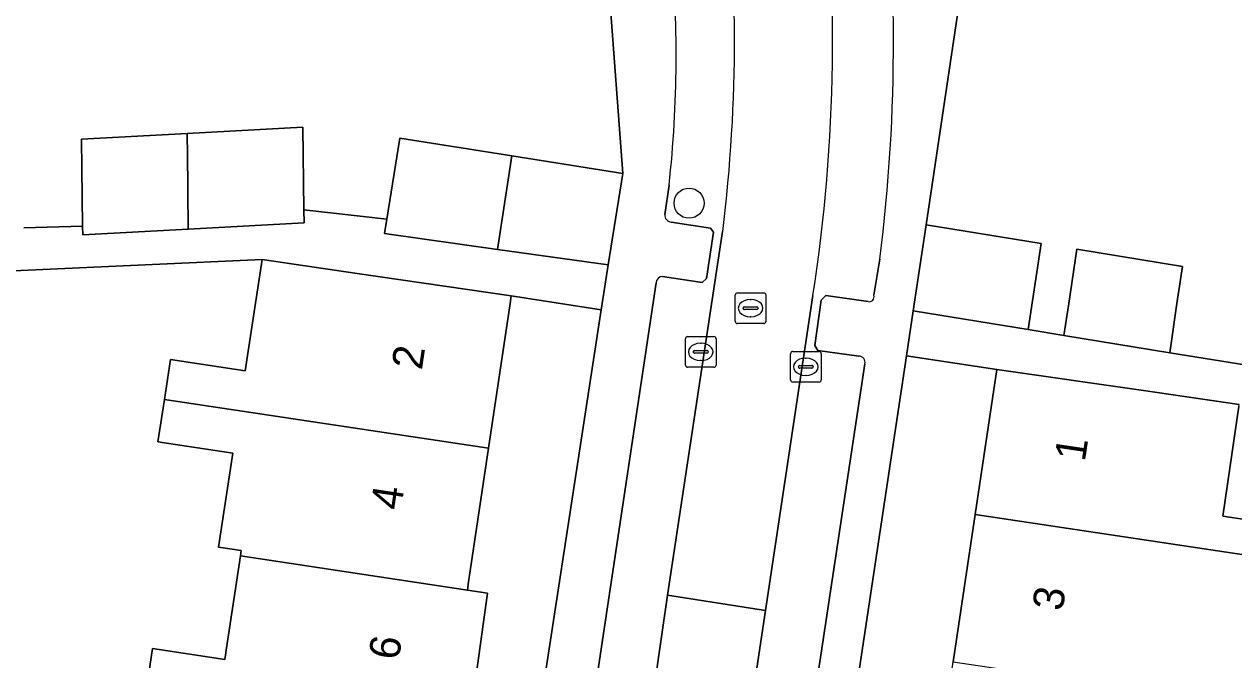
# Model space of a CAD drawing. Extents: x 162172 to 163187, y 382874 to 383685.
# Drawn here: x 162894.52 to 162933.89, y 383238.41 to 383259.09 of the extents above; entities that cross this region are included whole.
import ezdxf

# ---------------------------------------------------------------- set-up
doc = ezdxf.new("R2010")
doc.units = 0
for name, color, linetype in [('IMGEO_Boom', 7, 'Continuous'), ('IMGEO_Erf', 7, 'Continuous'), ('IMGEO_Kolk', 7, 'Continuous'), ('IMGEO_Muur', 7, 'Continuous'), ('IMGEO_Pand', 7, 'Continuous'), ('IMGEO_Pand_nummerreeks', 7, 'Continuous'), ('IMGEO_Parkeervlak_open', 7, 'Continuous'), ('IMGEO_Rijbaan_lokaal_open', 7, 'Continuous'), ('IMGEO_Rioolput', 7, 'Continuous'), ('IMGEO_Voetpad_open', 7, 'Continuous')]:
    doc.layers.add(name, color=color, linetype=linetype)

msp = doc.modelspace()

# ---------------------------------------------------------------- linework, layer by layer
at = {"layer": 'IMGEO_Boom'}
msp.add_circle((162916.16, 383253.265), 0.489, dxfattribs=at)
at = {"layer": 'IMGEO_Erf'}
for points in [[(162934.989, 383262.05), (162932.66, 383262.403), (162933.544, 383268.238), (162931.436, 383268.558), (162931.329, 383268.574), (162930.448, 383262.75), (162927.945, 383263.13), (162928.827, 383268.939), (162926.38, 383269.333), (162925.9, 383266.108), (162923.881, 383252.56), (162927.616, 383251.955), (162927.192, 383249.152), (162928.361, 383248.961), (162928.518, 383250), (162928.785, 383251.765), (162932.219, 383251.209), (162932.041, 383250), (162931.805, 383248.398), (162934.581, 383247.955)], [(162894.504, 383252.462), (162896.421, 383252.512), (162896.387, 383255.35), (162899.825, 383255.537), (162903.59, 383255.742), (162903.622, 383253.045), (162906.327, 383252.747), (162906.744, 383255.382), (162910.388, 383254.806), (162914.003, 383254.234), (162913.119, 383266.134), (162910.43, 383265.808), (162910.757, 383263.107), (162908.624, 383262.849), (162906.315, 383262.569), (162905.961, 383265.268), (162903.681, 383264.992), (162900.827, 383264.647), (162901.156, 383261.937), (162899.391, 383261.721), (162896.633, 383261.383), (162896.303, 383264.098), (162894.263, 383263.851)], [(162898.475, 383237.306), (162898.697, 383238.777), (162901.051, 383238.422), (162901.071, 383238.561), (162901.096, 383238.723), (162901.558, 383241.786), (162901.585, 383241.962), (162900.839, 383242.075), (162901.306, 383245.133), (162898.874, 383245.5), (162899.083, 383246.881), (162899.28, 383248.182), (162901.716, 383247.815), (162902.268, 383251.437), (162890.827, 383250.913)], [(162934.059, 383246.652), (162933.53, 383243.076), (162935.915, 383242.72)]]:
    msp.add_lwpolyline(points, dxfattribs=at)
for points in [[(162913.302, 383249.799), (162910.373, 383250.249), (162910.336, 383250), (162909.634, 383245.289), (162908.975, 383240.868), (162908.946, 383240.672), (162909.601, 383240.573), (162909.276, 383238.224), (162908.859, 383235.784), (162908.216, 383235.881), (162908.083, 383234.992), (162907.5, 383231.099), (162906.821, 383226.56), (162906.152, 383222.098), (162905.411, 383217.147), (162904.723, 383212.551), (162904.005, 383207.761), (162903.984, 383207.622), (162903.965, 383207.492), (162906.731, 383207.017)], [(162921.934, 383219.49), (162922.637, 383224.192), (162923.376, 383229.127), (162924.046, 383233.605), (162924.754, 383238.339), (162925.471, 383243.131), (162926.177, 383247.852), (162923.232, 383248.295), (162916.805, 383205.549), (162919.781, 383205.102), (162920.499, 383209.897), (162921.214, 383214.678)]]:
    msp.add_lwpolyline(points, close=True, dxfattribs=at)
at = {"layer": 'IMGEO_Kolk'}
for p, q in [((162916.039, 383247.999), (162916.039, 383248.851)), ((162916.114, 383248.925), (162916.966, 383248.925)), ((162917.04, 383248.851), (162917.04, 383247.999)), ((162916.298, 383248.419), (162916.298, 383248.431)), ((162916.736, 383248.382), (162916.338, 383248.382)), ((162916.341, 383248.468), (162916.739, 383248.468)), ((162916.527, 383248.705), (162916.552, 383248.705)), ((162916.782, 383248.431), (162916.782, 383248.419)), ((162919.461, 383247.516), (162919.461, 383248.368)), ((162919.536, 383248.442), (162920.388, 383248.442)), ((162920.462, 383248.368), (162920.462, 383247.516)), ((162916.55, 383248.145), (162916.525, 383248.145)), ((162919.72, 383247.936), (162919.72, 383247.948)), ((162919.763, 383247.985), (162920.161, 383247.985)), ((162919.949, 383248.222), (162919.974, 383248.222)), ((162920.204, 383247.948), (162920.204, 383247.936)), ((162916.966, 383247.925), (162916.114, 383247.925)), ((162920.158, 383247.899), (162919.76, 383247.899)), ((162919.972, 383247.662), (162919.947, 383247.662)), ((162920.388, 383247.442), (162919.536, 383247.442))]:
    msp.add_line(p, q, dxfattribs=at)
for points in [[(162916.039, 383247.999), (162916.039, 383248.851)], [(162916.114, 383248.925), (162916.966, 383248.925)], [(162917.04, 383248.851), (162917.04, 383247.999)], [(162919.461, 383247.516), (162919.461, 383248.368)], [(162919.536, 383248.442), (162920.388, 383248.442)], [(162920.462, 383248.368), (162920.462, 383247.516)], [(162916.966, 383247.925), (162916.114, 383247.925)], [(162920.388, 383247.442), (162919.536, 383247.442)]]:
    msp.add_lwpolyline(points, dxfattribs=at)
for centre, radius, start, end in [((162916.116, 383248.849), 0.0765, 91.552, 178.448), ((162916.116, 383248.849), 0.0765, 91.552, 178.448), ((162916.964, 383248.849), 0.0765, 1.552, 88.448), ((162916.964, 383248.849), 0.0765, 1.552, 88.448), ((162916.338, 383248.428), 0.0403, 85.8775, 175.7526), ((162916.335, 383248.418), 0.0366, 178.938, 274.7102), ((162916.739, 383248.425), 0.043, 264.8664, 352.4533), ((162916.743, 383248.43), 0.0386, 1.7309, 96.639), ((162919.538, 383248.366), 0.0765, 91.552, 178.448), ((162919.538, 383248.366), 0.0765, 91.552, 178.448), ((162920.386, 383248.366), 0.0765, 1.552, 88.448), ((162920.386, 383248.366), 0.0765, 1.552, 88.448), ((162916.116, 383248.001), 0.0765, 181.552, 268.448), ((162916.116, 383248.001), 0.0765, 181.552, 268.448), ((162916.964, 383248.001), 0.0765, 271.552, 358.448), ((162916.964, 383248.001), 0.0765, 271.552, 358.448), ((162919.76, 383247.945), 0.0403, 85.8775, 175.7526), ((162920.165, 383247.947), 0.0386, 1.7309, 96.639), ((162919.757, 383247.935), 0.0366, 178.938, 274.7102), ((162920.161, 383247.942), 0.043, 264.8664, 352.4533), ((162919.538, 383247.518), 0.0765, 181.552, 268.448), ((162919.538, 383247.518), 0.0765, 181.552, 268.448), ((162920.386, 383247.518), 0.0765, 271.552, 358.448), ((162920.386, 383247.518), 0.0765, 271.552, 358.448)]:
    msp.add_arc(centre, radius, start, end, dxfattribs=at)
for centre, major_axis, ratio, start_param, end_param in [((162916.526, 383248.425), (-0.387, 0.002), 0.722429, 4.712389, 7.853982), ((162916.551, 383248.425), (-0.39, 0.002), 0.717154, 1.570796, 4.712389), ((162919.948, 383247.942), (-0.387, 0.002), 0.722429, 4.712389, 7.853982), ((162919.973, 383247.942), (-0.39, 0.002), 0.717154, 1.570796, 4.712389)]:
    msp.add_ellipse(centre, major_axis=major_axis, ratio=ratio, start_param=start_param, end_param=end_param, dxfattribs=at)
at = {"layer": 'IMGEO_Muur'}
msp.add_lwpolyline([(162925.9, 383266.108), (162923.881, 383252.56)], dxfattribs=at)
at = {"layer": 'IMGEO_Pand'}
for points in [[(162899.825, 383255.537), (162896.387, 383255.35), (162896.421, 383252.512), (162896.424, 383252.237), (162899.862, 383252.424), (162899.832, 383254.946), (162899.827, 383255.392)], [(162899.825, 383255.537), (162899.827, 383255.392), (162899.832, 383254.946), (162899.862, 383252.424), (162903.627, 383252.628), (162903.622, 383253.045), (162903.59, 383255.742)], [(162910.388, 383254.806), (162906.744, 383255.382), (162906.327, 383252.747), (162906.252, 383252.276), (162909.921, 383251.76)], [(162910.388, 383254.806), (162909.921, 383251.76), (162913.526, 383251.254), (162914.003, 383254.234)], [(162923.881, 383252.56), (162923.453, 383249.764), (162927.192, 383249.152), (162927.616, 383251.955)], [(162928.785, 383251.765), (162928.518, 383250), (162928.361, 383248.961), (162931.805, 383248.398), (162932.041, 383250), (162932.219, 383251.209)], [(162910.336, 383250), (162910.373, 383250.249), (162905.353, 383250.976), (162902.268, 383251.437), (162901.716, 383247.815), (162899.28, 383248.182), (162899.083, 383246.881), (162909.634, 383245.289)], [(162934.059, 383246.652), (162934.068, 383246.713), (162930.949, 383247.174), (162926.177, 383247.852), (162925.471, 383243.131), (162933.364, 383241.952), (162935.749, 383241.596), (162935.915, 383242.72), (162933.53, 383243.076)], [(162909.634, 383245.289), (162899.083, 383246.881), (162898.874, 383245.5), (162901.306, 383245.133), (162900.839, 383242.075), (162901.585, 383241.962), (162901.558, 383241.786), (162908.946, 383240.672), (162908.975, 383240.868)], [(162935.749, 383241.596), (162933.364, 383241.952), (162925.471, 383243.131), (162924.754, 383238.339), (162932.94, 383237.13), (162933.12, 383237.104), (162935.043, 383236.82), (162935.241, 383238.16)], [(162909.601, 383240.573), (162908.946, 383240.672), (162901.558, 383241.786), (162901.096, 383238.723), (162901.071, 383238.561), (162901.051, 383238.422), (162898.697, 383238.777), (162898.475, 383237.306), (162900.101, 383237.061), (162900.835, 383236.994), (162908.216, 383235.881), (162908.859, 383235.784), (162909.276, 383238.224)]]:
    msp.add_lwpolyline(points, close=True, dxfattribs=at)
at = {"layer": 'IMGEO_Parkeervlak_open'}
for points in [[(162915.509, 383253.853), (162915.369, 383252.895)], [(162898.486, 383137.076), (162902.633, 383156.139), (162903.644, 383161.345), (162904.903, 383169.786), (162905.415, 383173.218), (162909.988, 383203.872), (162910.508, 383207.3), (162914.959, 383237.052), (162915.456, 383240.511), (162917.253, 383252.345)], [(162915.577, 383252.651), (162916.863, 383252.454), (162916.95, 383252.326), (162916.725, 383250.811), (162916.582, 383250.683), (162915.296, 383250.883)], [(162922.169, 383250.267), (162922.37, 383251.448)], [(162915.087, 383250.673), (162902.202, 383164.866), (162902.347, 383164.599), (162903.275, 383164.489)], [(162920.189, 383250.262), (162918.648, 383240.012), (162918.136, 383236.616), (162913.692, 383206.81), (162913.182, 383203.388), (162908.6, 383172.737), (162908.06, 383169.286), (162907.047, 383162.397)], [(162921.688, 383248.289), (162920.353, 383248.476), (162920.254, 383248.634), (162920.461, 383250.113), (162920.617, 383250.264), (162921.986, 383250.065)], [(162920.189, 383236.831), (162921.883, 383248.034)]]:
    msp.add_lwpolyline(points, dxfattribs=at)
for centre, radius, start, end in [((162867.05, 383258.465), 55.763, 352.771, 7.572), ((162867.914, 383258.475), 52.916, 351.0713, 7.4794), ((162867.382, 383258.547), 50.256, 352.911, 7.3876), ((162876.654, 383258.105), 39.087, 353.7542, 5.4239), ((162915.593, 383252.875), 0.224, 174.866, 266.0264), ((162915.308, 383250.662), 0.222, 93.1632, 177.1103), ((162922.027, 383250.212), 0.153, 254.5794, 21.0712), ((162921.679, 383248.08), 0.209, 347.3716, 87.4391)]:
    msp.add_arc(centre, radius, start, end, dxfattribs=at)
at = {"layer": 'IMGEO_Rijbaan_lokaal_open'}
msp.add_lwpolyline([(162917.253, 383252.345), (162915.456, 383240.511), (162918.648, 383240.012), (162920.189, 383250.262)], dxfattribs=at)
msp.add_lwpolyline([(162914.959, 383237.052), (162918.136, 383236.616), (162918.648, 383240.012), (162915.456, 383240.511)], close=True, dxfattribs=at)
for centre, radius, start, end in [((162867.914, 383258.475), 52.916, 351.0713, 7.4794), ((162867.382, 383258.547), 50.256, 352.911, 7.3876)]:
    msp.add_arc(centre, radius, start, end, dxfattribs=at)
at = {"layer": 'IMGEO_Rioolput'}
for p, q in [((162917.738, 383250.348), (162918.59, 383250.348)), ((162917.663, 383249.422), (162917.663, 383250.274)), ((162918.151, 383250.128), (162918.176, 383250.128)), ((162918.664, 383250.274), (162918.664, 383249.422)), ((162917.922, 383249.842), (162917.922, 383249.854)), ((162918.36, 383249.805), (162917.962, 383249.805)), ((162917.965, 383249.891), (162918.363, 383249.891)), ((162918.174, 383249.568), (162918.149, 383249.568)), ((162918.406, 383249.854), (162918.406, 383249.842)), ((162918.59, 383249.348), (162917.738, 383249.348))]:
    msp.add_line(p, q, dxfattribs=at)
for points in [[(162917.738, 383250.348), (162918.59, 383250.348)], [(162917.663, 383249.422), (162917.663, 383250.274)], [(162918.664, 383250.274), (162918.664, 383249.422)], [(162918.59, 383249.348), (162917.738, 383249.348)]]:
    msp.add_lwpolyline(points, dxfattribs=at)
for centre, radius, start, end in [((162917.74, 383250.272), 0.0765, 91.552, 178.448), ((162917.74, 383250.272), 0.0765, 91.552, 178.448), ((162918.588, 383250.272), 0.0765, 1.552, 88.448), ((162918.588, 383250.272), 0.0765, 1.552, 88.448), ((162917.962, 383249.851), 0.0403, 85.8775, 175.7526), ((162917.959, 383249.841), 0.0366, 178.938, 274.7102), ((162918.363, 383249.848), 0.043, 264.8664, 352.4533), ((162918.367, 383249.853), 0.0386, 1.7309, 96.639), ((162917.74, 383249.424), 0.0765, 181.552, 268.448), ((162917.74, 383249.424), 0.0765, 181.552, 268.448), ((162918.588, 383249.424), 0.0765, 271.552, 358.448), ((162918.588, 383249.424), 0.0765, 271.552, 358.448)]:
    msp.add_arc(centre, radius, start, end, dxfattribs=at)
for centre, major_axis, ratio, start_param, end_param in [((162918.15, 383249.848), (-0.387, 0.002), 0.722429, 4.712389, 7.853982), ((162918.175, 383249.848), (-0.39, 0.002), 0.717154, 1.570796, 4.712389)]:
    msp.add_ellipse(centre, major_axis=major_axis, ratio=ratio, start_param=start_param, end_param=end_param, dxfattribs=at)
at = {"layer": 'IMGEO_Voetpad_open'}
for points in [[(162909.545, 383157.158), (162909.977, 383160.133), (162910.196, 383161.591), (162916.594, 383204.144), (162916.805, 383205.549), (162923.232, 383248.295), (162923.453, 383249.764), (162923.881, 383252.56), (162925.9, 383266.108), (162924.036, 383265.899), (162923.136, 383274.356), (162919.612, 383273.145)], [(162915.566, 383261.8), (162914.441, 383273.117), (162912.274, 383273.237), (162913.119, 383266.134), (162914.003, 383254.234), (162913.526, 383251.254), (162913.333, 383250), (162913.302, 383249.799), (162906.731, 383207.017), (162906.539, 383205.766), (162906.505, 383205.532), (162900.276, 383163.119), (162900.06, 383161.648), (162900.192, 383161.628), (162899.697, 383158.408), (162898.651, 383153.856), (162897.653, 383149.297), (162895.206, 383138.052), (162894.584, 383138.19), (162894.525, 383137.704)], [(162915.369, 383252.895), (162915.509, 383253.853)], [(162890.827, 383250.913), (162902.268, 383251.437), (162905.353, 383250.976), (162910.373, 383250.249), (162913.302, 383249.799), (162913.333, 383250), (162913.526, 383251.254), (162909.921, 383251.76), (162906.252, 383252.276), (162906.327, 383252.747), (162903.622, 383253.045), (162903.627, 383252.628), (162899.862, 383252.424), (162896.424, 383252.237), (162896.421, 383252.512), (162894.504, 383252.462)], [(162915.296, 383250.883), (162916.582, 383250.683), (162916.725, 383250.811), (162916.95, 383252.326), (162916.863, 383252.454), (162915.577, 383252.651)], [(162922.37, 383251.448), (162922.169, 383250.267)], [(162903.275, 383164.489), (162902.347, 383164.599), (162902.202, 383164.866), (162915.087, 383250.673)], [(162921.986, 383250.065), (162920.617, 383250.264), (162920.461, 383250.113), (162920.254, 383248.634), (162920.353, 383248.476), (162921.688, 383248.289)], [(162934.581, 383247.955), (162931.805, 383248.398), (162928.361, 383248.961), (162927.192, 383249.152), (162923.453, 383249.764), (162923.232, 383248.295), (162926.177, 383247.852), (162930.949, 383247.174), (162934.068, 383246.713)], [(162921.883, 383248.034), (162920.189, 383236.831)]]:
    msp.add_lwpolyline(points, dxfattribs=at)
for centre, radius, start, end in [((162867.05, 383258.465), 55.763, 352.771, 7.572), ((162876.654, 383258.105), 39.087, 353.7542, 5.4239), ((162915.593, 383252.875), 0.224, 174.866, 266.0264), ((162915.308, 383250.662), 0.222, 93.1632, 177.1103), ((162922.027, 383250.212), 0.153, 254.5794, 21.0712), ((162921.679, 383248.08), 0.209, 347.3716, 87.4391)]:
    msp.add_arc(centre, radius, start, end, dxfattribs=at)

# ---------------------------------------------------------------- texts
at = {"layer": 'IMGEO_Pand_nummerreeks'}
for s, rotation, p in [('2', 81.5262, (162907.462, 383247.814)), ('1', 81.4918, (162929.042, 383244.832)), ('4', 81.5262, (162906.782, 383243.25)), ('3', 81.4918, (162928.314, 383239.969)), ('6', 81.2282, (162906.708, 383238.371))]:
    msp.add_text(s, height=1, rotation=rotation, dxfattribs=at).set_placement(p)

doc.saveas('drawing.dxf')
